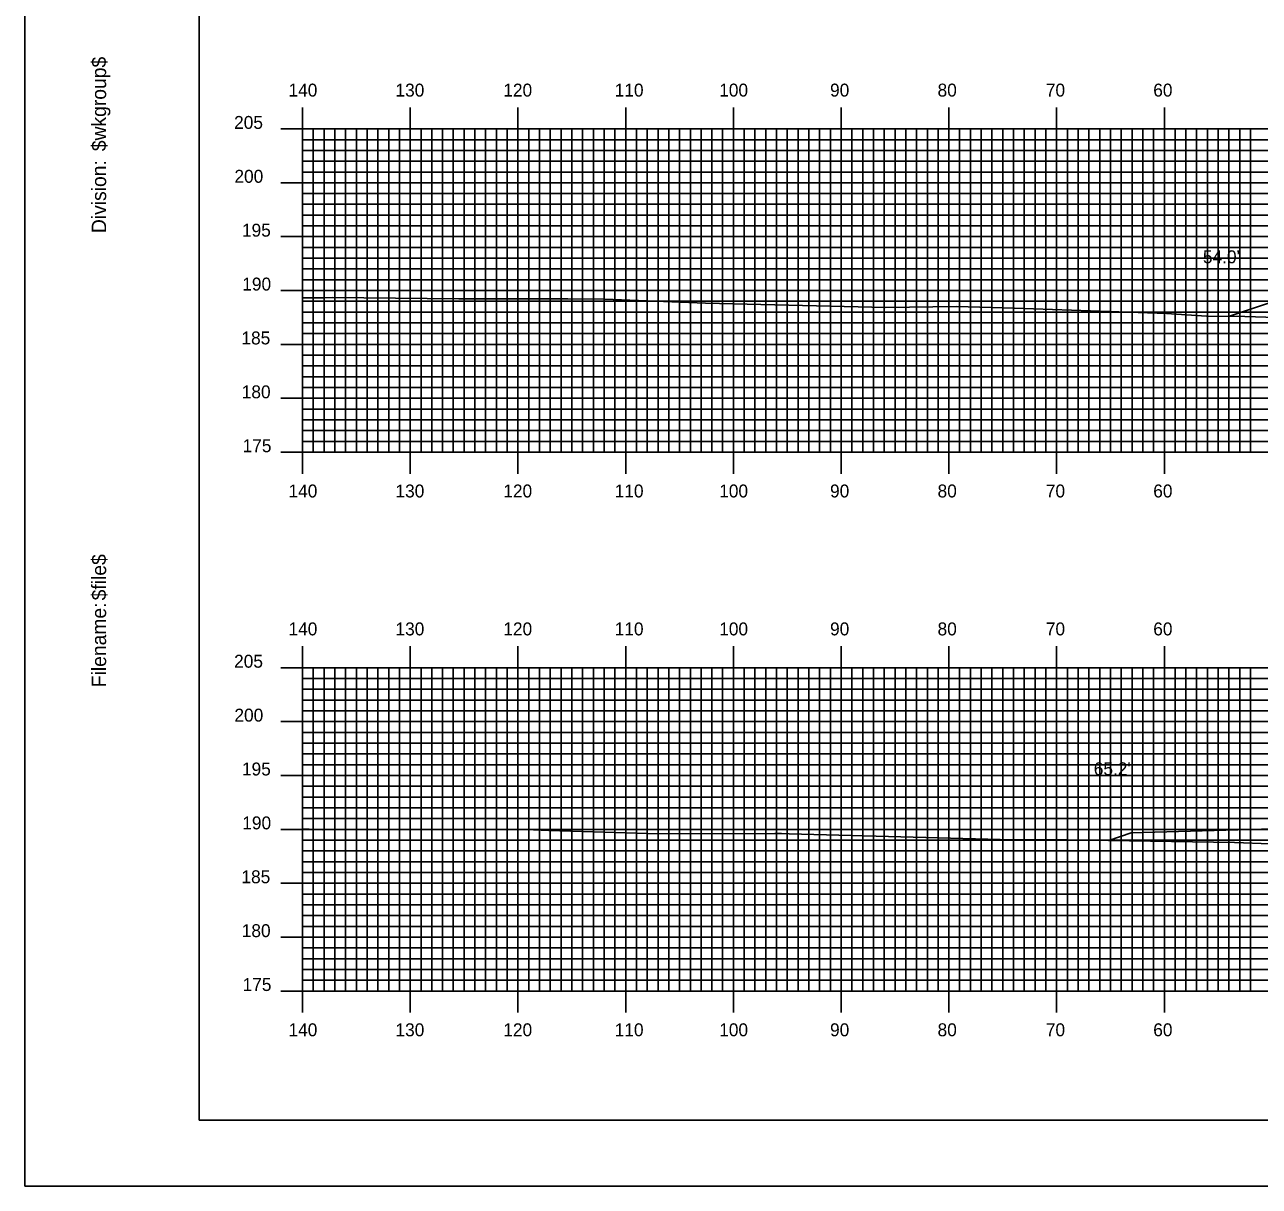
# Model space of a CAD drawing. Extents: x 1808226 to 1808569, y 442591 to 442811.
# Drawn here: x 1808225.5 to 1808340.1, y 442590.5 to 442698.3 of the extents above; entities that cross this region are included whole.
import ezdxf

# ---------------------------------------------------------------- set-up
doc = ezdxf.new("R2010")
doc.units = 0
for name, color, linetype in [('BORDER', 7, 'Continuous'), ('D_Roadway_Centerline', 7, 'Continuous'), ('D_Roadway_SlopeLines', 7, 'Continuous'), ('D_Text_Standard', 7, 'Continuous'), ('H_V ANNOTATION', 7, 'Continuous'), ('MAJOR', 7, 'Continuous'), ('MINOR', 7, 'Continuous'), ('PLOT BOUNDARY', 7, 'Continuous'), ('S_Roadway_Centerline', 7, 'Continuous')]:
    doc.layers.add(name, color=color, linetype=linetype)

msp = doc.modelspace()

# ---------------------------------------------------------------- linework, layer by layer
at = {"layer": 'BORDER'}
msp.add_lwpolyline([(1808241.7, 442596.67), (1808561.7, 442596.67), (1808561.7, 442806.67), (1808241.7, 442806.67)], close=True, dxfattribs=at)
at = {"layer": 'D_Roadway_Centerline'}
msp.add_lwpolyline([(1808337.34, 442671.28), (1808359.3, 442678.6), (1808362.94, 442679.51), (1808371.3, 442681.6), (1808379.3, 442681.92), (1808391.3, 442682.16), (1808403.3, 442681.92), (1808420.74, 442681.22), (1808428.28, 442679.33), (1808432.74, 442678.22), (1808464.21, 442667.73)], dxfattribs=at)
at = {"layer": 'D_Roadway_SlopeLines'}
for points in [[(1808371.3, 442681.6), (1808359.3, 442678.6), (1808337.34, 442671.28)], [(1808344.71, 442623.81), (1808328.23, 442623.34), (1808326.14, 442622.64)]]:
    msp.add_lwpolyline(points, dxfattribs=at)
at = {"layer": 'MAJOR'}
for p, q in [((1808251.3, 442690.67), (1808251.3, 442688.67)), ((1808261.3, 442690.67), (1808261.3, 442688.67)), ((1808271.3, 442690.67), (1808271.3, 442688.67)), ((1808281.3, 442690.67), (1808281.3, 442688.67)), ((1808291.3, 442690.67), (1808291.3, 442688.67)), ((1808301.3, 442690.67), (1808301.3, 442688.67)), ((1808311.3, 442690.67), (1808311.3, 442688.67)), ((1808321.3, 442690.67), (1808321.3, 442688.67)), ((1808331.3, 442690.67), (1808331.3, 442688.67)), ((1808249.29, 442688.67), (1808251.3, 442688.67)), ((1808251.3, 442688.67), (1808531.3, 442688.67)), ((1808251.3, 442658.67), (1808251.3, 442688.67)), ((1808251.3, 442658.67), (1808251.3, 442688.67)), ((1808251.3, 442688.67), (1808531.3, 442688.67)), ((1808261.3, 442658.67), (1808261.3, 442688.67)), ((1808271.3, 442658.67), (1808271.3, 442688.67)), ((1808281.3, 442658.67), (1808281.3, 442688.67)), ((1808291.3, 442658.67), (1808291.3, 442688.67)), ((1808301.3, 442658.67), (1808301.3, 442688.67)), ((1808311.3, 442658.67), (1808311.3, 442688.67)), ((1808321.3, 442658.67), (1808321.3, 442688.67)), ((1808331.3, 442658.67), (1808331.3, 442688.67)), ((1808249.29, 442683.67), (1808251.3, 442683.67)), ((1808251.3, 442683.67), (1808531.3, 442683.67)), ((1808249.29, 442678.67), (1808251.3, 442678.67)), ((1808251.3, 442678.67), (1808531.3, 442678.67)), ((1808249.29, 442673.67), (1808251.3, 442673.67)), ((1808251.3, 442673.67), (1808531.3, 442673.67)), ((1808249.29, 442668.67), (1808251.3, 442668.67)), ((1808251.3, 442668.67), (1808531.3, 442668.67)), ((1808249.29, 442663.67), (1808251.3, 442663.67)), ((1808251.3, 442663.67), (1808531.3, 442663.67)), ((1808249.29, 442658.67), (1808251.3, 442658.67)), ((1808251.3, 442658.67), (1808531.3, 442658.67)), ((1808251.3, 442658.67), (1808531.3, 442658.67)), ((1808251.3, 442656.66), (1808251.3, 442658.67)), ((1808261.3, 442656.66), (1808261.3, 442658.67)), ((1808271.3, 442656.66), (1808271.3, 442658.67)), ((1808281.3, 442656.66), (1808281.3, 442658.67)), ((1808291.3, 442656.66), (1808291.3, 442658.67)), ((1808301.3, 442656.66), (1808301.3, 442658.67)), ((1808311.3, 442656.66), (1808311.3, 442658.67)), ((1808321.3, 442656.66), (1808321.3, 442658.67)), ((1808331.3, 442656.66), (1808331.3, 442658.67)), ((1808251.3, 442640.67), (1808251.3, 442638.67)), ((1808261.3, 442640.67), (1808261.3, 442638.67)), ((1808271.3, 442640.67), (1808271.3, 442638.67)), ((1808281.3, 442640.67), (1808281.3, 442638.67)), ((1808291.3, 442640.67), (1808291.3, 442638.67)), ((1808301.3, 442640.67), (1808301.3, 442638.67)), ((1808311.3, 442640.67), (1808311.3, 442638.67)), ((1808321.3, 442640.67), (1808321.3, 442638.67)), ((1808331.3, 442640.67), (1808331.3, 442638.67)), ((1808249.29, 442638.67), (1808251.3, 442638.67)), ((1808251.3, 442638.67), (1808531.3, 442638.67)), ((1808251.3, 442608.67), (1808251.3, 442638.67)), ((1808251.3, 442608.67), (1808251.3, 442638.67)), ((1808251.3, 442638.67), (1808531.3, 442638.67)), ((1808261.3, 442608.67), (1808261.3, 442638.67)), ((1808271.3, 442608.67), (1808271.3, 442638.67)), ((1808281.3, 442608.67), (1808281.3, 442638.67)), ((1808291.3, 442608.67), (1808291.3, 442638.67)), ((1808301.3, 442608.67), (1808301.3, 442638.67)), ((1808311.3, 442608.67), (1808311.3, 442638.67)), ((1808321.3, 442608.67), (1808321.3, 442638.67)), ((1808331.3, 442608.67), (1808331.3, 442638.67)), ((1808249.29, 442633.67), (1808251.3, 442633.67)), ((1808251.3, 442633.67), (1808531.3, 442633.67)), ((1808249.29, 442628.67), (1808251.3, 442628.67)), ((1808251.3, 442628.67), (1808531.3, 442628.67)), ((1808249.29, 442623.67), (1808251.3, 442623.67)), ((1808251.3, 442623.67), (1808531.3, 442623.67)), ((1808249.29, 442618.67), (1808251.3, 442618.67)), ((1808251.3, 442618.67), (1808531.3, 442618.67)), ((1808249.29, 442613.67), (1808251.3, 442613.67)), ((1808251.3, 442613.67), (1808531.3, 442613.67)), ((1808249.29, 442608.67), (1808251.3, 442608.67)), ((1808251.3, 442608.67), (1808531.3, 442608.67)), ((1808251.3, 442608.67), (1808531.3, 442608.67)), ((1808251.3, 442606.66), (1808251.3, 442608.67)), ((1808261.3, 442606.66), (1808261.3, 442608.67)), ((1808271.3, 442606.66), (1808271.3, 442608.67)), ((1808281.3, 442606.66), (1808281.3, 442608.67)), ((1808291.3, 442606.66), (1808291.3, 442608.67)), ((1808301.3, 442606.66), (1808301.3, 442608.67)), ((1808311.3, 442606.66), (1808311.3, 442608.67)), ((1808321.3, 442606.66), (1808321.3, 442608.67)), ((1808331.3, 442606.66), (1808331.3, 442608.67))]:
    msp.add_line(p, q, dxfattribs=at)
at = {"layer": 'MINOR'}
for p, q in [((1808252.3, 442658.67), (1808252.3, 442688.67)), ((1808253.3, 442658.67), (1808253.3, 442688.67)), ((1808254.3, 442658.67), (1808254.3, 442688.67)), ((1808255.3, 442658.67), (1808255.3, 442688.67)), ((1808256.3, 442658.67), (1808256.3, 442688.67)), ((1808257.3, 442658.67), (1808257.3, 442688.67)), ((1808258.3, 442658.67), (1808258.3, 442688.67)), ((1808259.3, 442658.67), (1808259.3, 442688.67)), ((1808260.3, 442658.67), (1808260.3, 442688.67)), ((1808262.3, 442658.67), (1808262.3, 442688.67)), ((1808263.3, 442658.67), (1808263.3, 442688.67)), ((1808264.3, 442658.67), (1808264.3, 442688.67)), ((1808265.3, 442658.67), (1808265.3, 442688.67)), ((1808266.3, 442658.67), (1808266.3, 442688.67)), ((1808267.3, 442658.67), (1808267.3, 442688.67)), ((1808268.3, 442658.67), (1808268.3, 442688.67)), ((1808269.3, 442658.67), (1808269.3, 442688.67)), ((1808270.3, 442658.67), (1808270.3, 442688.67)), ((1808272.3, 442658.67), (1808272.3, 442688.67)), ((1808273.3, 442658.67), (1808273.3, 442688.67)), ((1808274.3, 442658.67), (1808274.3, 442688.67)), ((1808275.3, 442658.67), (1808275.3, 442688.67)), ((1808276.3, 442658.67), (1808276.3, 442688.67)), ((1808277.3, 442658.67), (1808277.3, 442688.67)), ((1808278.3, 442658.67), (1808278.3, 442688.67)), ((1808279.3, 442658.67), (1808279.3, 442688.67)), ((1808280.3, 442658.67), (1808280.3, 442688.67)), ((1808282.3, 442658.67), (1808282.3, 442688.67)), ((1808283.3, 442658.67), (1808283.3, 442688.67)), ((1808284.3, 442658.67), (1808284.3, 442688.67)), ((1808285.3, 442658.67), (1808285.3, 442688.67)), ((1808286.3, 442658.67), (1808286.3, 442688.67)), ((1808287.3, 442658.67), (1808287.3, 442688.67)), ((1808288.3, 442658.67), (1808288.3, 442688.67)), ((1808289.3, 442658.67), (1808289.3, 442688.67)), ((1808290.3, 442658.67), (1808290.3, 442688.67)), ((1808292.3, 442658.67), (1808292.3, 442688.67)), ((1808293.3, 442658.67), (1808293.3, 442688.67)), ((1808294.3, 442658.67), (1808294.3, 442688.67)), ((1808295.3, 442658.67), (1808295.3, 442688.67)), ((1808296.3, 442658.67), (1808296.3, 442688.67)), ((1808297.3, 442658.67), (1808297.3, 442688.67)), ((1808298.3, 442658.67), (1808298.3, 442688.67)), ((1808299.3, 442658.67), (1808299.3, 442688.67)), ((1808300.3, 442658.67), (1808300.3, 442688.67)), ((1808302.3, 442658.67), (1808302.3, 442688.67)), ((1808303.3, 442658.67), (1808303.3, 442688.67)), ((1808304.3, 442658.67), (1808304.3, 442688.67)), ((1808305.3, 442658.67), (1808305.3, 442688.67)), ((1808306.3, 442658.67), (1808306.3, 442688.67)), ((1808307.3, 442658.67), (1808307.3, 442688.67)), ((1808308.3, 442658.67), (1808308.3, 442688.67)), ((1808309.3, 442658.67), (1808309.3, 442688.67)), ((1808310.3, 442658.67), (1808310.3, 442688.67)), ((1808312.3, 442658.67), (1808312.3, 442688.67)), ((1808313.3, 442658.67), (1808313.3, 442688.67)), ((1808314.3, 442658.67), (1808314.3, 442688.67)), ((1808315.3, 442658.67), (1808315.3, 442688.67)), ((1808316.3, 442658.67), (1808316.3, 442688.67)), ((1808317.3, 442658.67), (1808317.3, 442688.67)), ((1808318.3, 442658.67), (1808318.3, 442688.67)), ((1808319.3, 442658.67), (1808319.3, 442688.67)), ((1808320.3, 442658.67), (1808320.3, 442688.67)), ((1808322.3, 442658.67), (1808322.3, 442688.67)), ((1808323.3, 442658.67), (1808323.3, 442688.67)), ((1808324.3, 442658.67), (1808324.3, 442688.67)), ((1808325.3, 442658.67), (1808325.3, 442688.67)), ((1808326.3, 442658.67), (1808326.3, 442688.67)), ((1808327.3, 442658.67), (1808327.3, 442688.67)), ((1808328.3, 442658.67), (1808328.3, 442688.67)), ((1808329.3, 442658.67), (1808329.3, 442688.67)), ((1808330.3, 442658.67), (1808330.3, 442688.67)), ((1808332.3, 442658.67), (1808332.3, 442688.67)), ((1808333.3, 442658.67), (1808333.3, 442688.67)), ((1808334.3, 442658.67), (1808334.3, 442688.67)), ((1808335.3, 442658.67), (1808335.3, 442688.67)), ((1808336.3, 442658.67), (1808336.3, 442688.67)), ((1808337.3, 442658.67), (1808337.3, 442688.67)), ((1808338.3, 442658.67), (1808338.3, 442688.67)), ((1808339.3, 442658.67), (1808339.3, 442688.67)), ((1808251.3, 442687.67), (1808531.3, 442687.67)), ((1808251.3, 442687.67), (1808253.3, 442687.67)), ((1808251.3, 442686.67), (1808531.3, 442686.67)), ((1808251.3, 442686.67), (1808253.3, 442686.67)), ((1808251.3, 442685.67), (1808531.3, 442685.67)), ((1808251.3, 442685.67), (1808253.3, 442685.67)), ((1808251.3, 442684.67), (1808531.3, 442684.67)), ((1808251.3, 442684.67), (1808253.3, 442684.67)), ((1808251.3, 442682.67), (1808531.3, 442682.67)), ((1808251.3, 442682.67), (1808253.3, 442682.67)), ((1808251.3, 442681.67), (1808531.3, 442681.67)), ((1808251.3, 442681.67), (1808253.3, 442681.67)), ((1808251.3, 442680.67), (1808531.3, 442680.67)), ((1808251.3, 442680.67), (1808253.3, 442680.67)), ((1808251.3, 442679.67), (1808531.3, 442679.67)), ((1808251.3, 442679.67), (1808253.3, 442679.67)), ((1808251.3, 442677.67), (1808531.3, 442677.67)), ((1808251.3, 442677.67), (1808253.3, 442677.67)), ((1808251.3, 442676.67), (1808531.3, 442676.67)), ((1808251.3, 442676.67), (1808253.3, 442676.67)), ((1808251.3, 442675.67), (1808531.3, 442675.67)), ((1808251.3, 442675.67), (1808253.3, 442675.67)), ((1808251.3, 442674.67), (1808531.3, 442674.67)), ((1808251.3, 442674.67), (1808253.3, 442674.67)), ((1808251.3, 442672.67), (1808531.3, 442672.67)), ((1808251.3, 442672.67), (1808253.3, 442672.67)), ((1808251.3, 442671.67), (1808531.3, 442671.67)), ((1808251.3, 442671.67), (1808253.3, 442671.67)), ((1808251.3, 442670.67), (1808531.3, 442670.67)), ((1808251.3, 442670.67), (1808253.3, 442670.67)), ((1808251.3, 442669.67), (1808531.3, 442669.67)), ((1808251.3, 442669.67), (1808253.3, 442669.67)), ((1808251.3, 442667.67), (1808531.3, 442667.67)), ((1808251.3, 442667.67), (1808253.3, 442667.67)), ((1808251.3, 442666.67), (1808531.3, 442666.67)), ((1808251.3, 442666.67), (1808253.3, 442666.67)), ((1808251.3, 442665.67), (1808531.3, 442665.67)), ((1808251.3, 442665.67), (1808253.3, 442665.67)), ((1808251.3, 442664.67), (1808531.3, 442664.67)), ((1808251.3, 442664.67), (1808253.3, 442664.67)), ((1808251.3, 442662.67), (1808531.3, 442662.67)), ((1808251.3, 442662.67), (1808253.3, 442662.67)), ((1808251.3, 442661.67), (1808531.3, 442661.67)), ((1808251.3, 442661.67), (1808253.3, 442661.67)), ((1808251.3, 442660.67), (1808531.3, 442660.67)), ((1808251.3, 442660.67), (1808253.3, 442660.67)), ((1808251.3, 442659.67), (1808531.3, 442659.67)), ((1808251.3, 442659.67), (1808253.3, 442659.67)), ((1808252.3, 442608.67), (1808252.3, 442638.67)), ((1808253.3, 442608.67), (1808253.3, 442638.67)), ((1808254.3, 442608.67), (1808254.3, 442638.67)), ((1808255.3, 442608.67), (1808255.3, 442638.67)), ((1808256.3, 442608.67), (1808256.3, 442638.67)), ((1808257.3, 442608.67), (1808257.3, 442638.67)), ((1808258.3, 442608.67), (1808258.3, 442638.67)), ((1808259.3, 442608.67), (1808259.3, 442638.67)), ((1808260.3, 442608.67), (1808260.3, 442638.67)), ((1808262.3, 442608.67), (1808262.3, 442638.67)), ((1808263.3, 442608.67), (1808263.3, 442638.67)), ((1808264.3, 442608.67), (1808264.3, 442638.67)), ((1808265.3, 442608.67), (1808265.3, 442638.67)), ((1808266.3, 442608.67), (1808266.3, 442638.67)), ((1808267.3, 442608.67), (1808267.3, 442638.67)), ((1808268.3, 442608.67), (1808268.3, 442638.67)), ((1808269.3, 442608.67), (1808269.3, 442638.67)), ((1808270.3, 442608.67), (1808270.3, 442638.67)), ((1808272.3, 442608.67), (1808272.3, 442638.67)), ((1808273.3, 442608.67), (1808273.3, 442638.67)), ((1808274.3, 442608.67), (1808274.3, 442638.67)), ((1808275.3, 442608.67), (1808275.3, 442638.67)), ((1808276.3, 442608.67), (1808276.3, 442638.67)), ((1808277.3, 442608.67), (1808277.3, 442638.67)), ((1808278.3, 442608.67), (1808278.3, 442638.67)), ((1808279.3, 442608.67), (1808279.3, 442638.67)), ((1808280.3, 442608.67), (1808280.3, 442638.67)), ((1808282.3, 442608.67), (1808282.3, 442638.67)), ((1808283.3, 442608.67), (1808283.3, 442638.67)), ((1808284.3, 442608.67), (1808284.3, 442638.67)), ((1808285.3, 442608.67), (1808285.3, 442638.67)), ((1808286.3, 442608.67), (1808286.3, 442638.67)), ((1808287.3, 442608.67), (1808287.3, 442638.67)), ((1808288.3, 442608.67), (1808288.3, 442638.67)), ((1808289.3, 442608.67), (1808289.3, 442638.67)), ((1808290.3, 442608.67), (1808290.3, 442638.67)), ((1808292.3, 442608.67), (1808292.3, 442638.67)), ((1808293.3, 442608.67), (1808293.3, 442638.67)), ((1808294.3, 442608.67), (1808294.3, 442638.67)), ((1808295.3, 442608.67), (1808295.3, 442638.67)), ((1808296.3, 442608.67), (1808296.3, 442638.67)), ((1808297.3, 442608.67), (1808297.3, 442638.67)), ((1808298.3, 442608.67), (1808298.3, 442638.67)), ((1808299.3, 442608.67), (1808299.3, 442638.67)), ((1808300.3, 442608.67), (1808300.3, 442638.67)), ((1808302.3, 442608.67), (1808302.3, 442638.67)), ((1808303.3, 442608.67), (1808303.3, 442638.67)), ((1808304.3, 442608.67), (1808304.3, 442638.67)), ((1808305.3, 442608.67), (1808305.3, 442638.67)), ((1808306.3, 442608.67), (1808306.3, 442638.67)), ((1808307.3, 442608.67), (1808307.3, 442638.67)), ((1808308.3, 442608.67), (1808308.3, 442638.67)), ((1808309.3, 442608.67), (1808309.3, 442638.67)), ((1808310.3, 442608.67), (1808310.3, 442638.67)), ((1808312.3, 442608.67), (1808312.3, 442638.67)), ((1808313.3, 442608.67), (1808313.3, 442638.67)), ((1808314.3, 442608.67), (1808314.3, 442638.67)), ((1808315.3, 442608.67), (1808315.3, 442638.67)), ((1808316.3, 442608.67), (1808316.3, 442638.67)), ((1808317.3, 442608.67), (1808317.3, 442638.67)), ((1808318.3, 442608.67), (1808318.3, 442638.67)), ((1808319.3, 442608.67), (1808319.3, 442638.67)), ((1808320.3, 442608.67), (1808320.3, 442638.67)), ((1808322.3, 442608.67), (1808322.3, 442638.67)), ((1808323.3, 442608.67), (1808323.3, 442638.67)), ((1808324.3, 442608.67), (1808324.3, 442638.67)), ((1808325.3, 442608.67), (1808325.3, 442638.67)), ((1808326.3, 442608.67), (1808326.3, 442638.67)), ((1808327.3, 442608.67), (1808327.3, 442638.67)), ((1808328.3, 442608.67), (1808328.3, 442638.67)), ((1808329.3, 442608.67), (1808329.3, 442638.67)), ((1808330.3, 442608.67), (1808330.3, 442638.67)), ((1808332.3, 442608.67), (1808332.3, 442638.67)), ((1808333.3, 442608.67), (1808333.3, 442638.67)), ((1808334.3, 442608.67), (1808334.3, 442638.67)), ((1808335.3, 442608.67), (1808335.3, 442638.67)), ((1808336.3, 442608.67), (1808336.3, 442638.67)), ((1808337.3, 442608.67), (1808337.3, 442638.67)), ((1808338.3, 442608.67), (1808338.3, 442638.67)), ((1808339.3, 442608.67), (1808339.3, 442638.67)), ((1808251.3, 442637.67), (1808531.3, 442637.67)), ((1808251.3, 442637.67), (1808253.3, 442637.67)), ((1808251.3, 442636.67), (1808531.3, 442636.67)), ((1808251.3, 442636.67), (1808253.3, 442636.67)), ((1808251.3, 442635.67), (1808531.3, 442635.67)), ((1808251.3, 442635.67), (1808253.3, 442635.67)), ((1808251.3, 442634.67), (1808531.3, 442634.67)), ((1808251.3, 442634.67), (1808253.3, 442634.67)), ((1808251.3, 442632.67), (1808531.3, 442632.67)), ((1808251.3, 442632.67), (1808253.3, 442632.67)), ((1808251.3, 442631.67), (1808531.3, 442631.67)), ((1808251.3, 442631.67), (1808253.3, 442631.67)), ((1808251.3, 442630.67), (1808531.3, 442630.67)), ((1808251.3, 442630.67), (1808253.3, 442630.67)), ((1808251.3, 442629.67), (1808531.3, 442629.67)), ((1808251.3, 442629.67), (1808253.3, 442629.67)), ((1808251.3, 442627.67), (1808531.3, 442627.67)), ((1808251.3, 442627.67), (1808253.3, 442627.67)), ((1808251.3, 442626.67), (1808531.3, 442626.67)), ((1808251.3, 442626.67), (1808253.3, 442626.67)), ((1808251.3, 442625.67), (1808531.3, 442625.67)), ((1808251.3, 442625.67), (1808253.3, 442625.67)), ((1808251.3, 442624.67), (1808531.3, 442624.67)), ((1808251.3, 442624.67), (1808253.3, 442624.67)), ((1808251.3, 442622.67), (1808531.3, 442622.67)), ((1808251.3, 442622.67), (1808253.3, 442622.67)), ((1808251.3, 442621.67), (1808531.3, 442621.67)), ((1808251.3, 442621.67), (1808253.3, 442621.67)), ((1808251.3, 442620.67), (1808531.3, 442620.67)), ((1808251.3, 442620.67), (1808253.3, 442620.67)), ((1808251.3, 442619.67), (1808531.3, 442619.67)), ((1808251.3, 442619.67), (1808253.3, 442619.67)), ((1808251.3, 442617.67), (1808531.3, 442617.67)), ((1808251.3, 442617.67), (1808253.3, 442617.67)), ((1808251.3, 442616.67), (1808531.3, 442616.67)), ((1808251.3, 442616.67), (1808253.3, 442616.67)), ((1808251.3, 442615.67), (1808531.3, 442615.67)), ((1808251.3, 442615.67), (1808253.3, 442615.67)), ((1808251.3, 442614.67), (1808531.3, 442614.67)), ((1808251.3, 442614.67), (1808253.3, 442614.67)), ((1808251.3, 442612.67), (1808531.3, 442612.67)), ((1808251.3, 442612.67), (1808253.3, 442612.67)), ((1808251.3, 442611.67), (1808531.3, 442611.67)), ((1808251.3, 442611.67), (1808253.3, 442611.67)), ((1808251.3, 442610.67), (1808531.3, 442610.67)), ((1808251.3, 442610.67), (1808253.3, 442610.67)), ((1808251.3, 442609.67), (1808531.3, 442609.67)), ((1808251.3, 442609.67), (1808253.3, 442609.67))]:
    msp.add_line(p, q, dxfattribs=at)
at = {"layer": 'PLOT BOUNDARY'}
msp.add_lwpolyline([(1808225.51, 442590.55), (1808565.51, 442590.55), (1808565.51, 442810.55), (1808225.51, 442810.55)], close=True, dxfattribs=at)
at = {"layer": 'S_Roadway_Centerline'}
for points in [[(1808251.3, 442673), (1808252.32, 442672.99), (1808253.21, 442673), (1808254.04, 442673.01), (1808265.82, 442672.91), (1808275.94, 442672.91), (1808279.36, 442672.86), (1808288.71, 442672.49), (1808305.46, 442672.09), (1808312, 442672.18), (1808317.38, 442672.03), (1808331.49, 442671.53), (1808335.21, 442671.29), (1808338.78, 442671.27), (1808356.45, 442670.7)], [(1808251.3, 442623.71), (1808253.15, 442623.62), (1808269.35, 442623.7), (1808272.04, 442623.65), (1808274.17, 442623.57), (1808284.38, 442623.24), (1808295.14, 442623.28), (1808295.76, 442623.27), (1808296.47, 442623.25), (1808316.05, 442622.72), (1808318.83, 442622.7), (1808322.21, 442622.7), (1808337.8, 442622.46), (1808347.76, 442622.08)]]:
    msp.add_lwpolyline(points, dxfattribs=at)

# ---------------------------------------------------------------- texts
at = {"layer": 'BORDER'}
for s, p in [('$wkgroup$', (1808233.07, 442686.6)), ('Division:', (1808233.07, 442679)), ('$file$', (1808233.07, 442644.92)), ('Filename:', (1808233.07, 442636.86))]:
    msp.add_text(s, height=1.339, rotation=90, dxfattribs=at).set_placement(p)
at = {"layer": 'D_Text_Standard'}
for s, p in [("54.0'", (1808334.88, 442676.2)), ("65.2'", (1808324.75, 442628.69))]:
    msp.add_text(s, height=1.2, dxfattribs=at).set_placement(p)
at = {"layer": 'H_V ANNOTATION'}
for s, p in [('140', (1808250, 442691.67)), ('130', (1808259.93, 442691.67)), ('120', (1808269.94, 442691.67)), ('110', (1808280.28, 442691.67)), ('100', (1808289.98, 442691.67)), ('90', (1808300.27, 442691.67)), ('80', (1808310.25, 442691.67)), ('70', (1808320.3, 442691.67)), ('60', (1808330.27, 442691.67)), ('205', (1808244.95, 442688.67)), ('200', (1808244.98, 442683.67)), ('195', (1808245.68, 442678.67)), ('190', (1808245.71, 442673.67)), ('185', (1808245.63, 442668.67)), ('180', (1808245.66, 442663.67)), ('175', (1808245.74, 442658.67)), ('140', (1808250, 442654.47)), ('130', (1808259.93, 442654.47)), ('120', (1808269.94, 442654.47)), ('110', (1808280.28, 442654.47)), ('100', (1808289.98, 442654.47)), ('90', (1808300.27, 442654.47)), ('80', (1808310.25, 442654.47)), ('70', (1808320.3, 442654.47)), ('60', (1808330.27, 442654.47)), ('140', (1808250, 442641.67)), ('130', (1808259.93, 442641.67)), ('120', (1808269.94, 442641.67)), ('110', (1808280.28, 442641.67)), ('100', (1808289.98, 442641.67)), ('90', (1808300.27, 442641.67)), ('80', (1808310.25, 442641.67)), ('70', (1808320.3, 442641.67)), ('60', (1808330.27, 442641.67)), ('205', (1808244.95, 442638.67)), ('200', (1808244.98, 442633.67)), ('195', (1808245.68, 442628.67)), ('190', (1808245.71, 442623.67)), ('185', (1808245.63, 442618.67)), ('180', (1808245.66, 442613.67)), ('175', (1808245.74, 442608.67)), ('140', (1808250, 442604.47)), ('130', (1808259.93, 442604.47)), ('120', (1808269.94, 442604.47)), ('110', (1808280.28, 442604.47)), ('100', (1808289.98, 442604.47)), ('90', (1808300.27, 442604.47)), ('80', (1808310.25, 442604.47)), ('70', (1808320.3, 442604.47)), ('60', (1808330.27, 442604.47))]:
    msp.add_text(s, height=1.2, dxfattribs=at).set_placement(p)
at = {"layer": 'MAJOR'}
for p in [(1808251.29, 442658.67), (1808251.29, 442608.67)]:
    msp.add_text('-', height=0.012, dxfattribs=at).set_placement(p)

doc.saveas('drawing.dxf')
